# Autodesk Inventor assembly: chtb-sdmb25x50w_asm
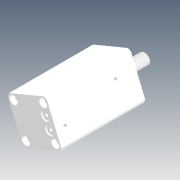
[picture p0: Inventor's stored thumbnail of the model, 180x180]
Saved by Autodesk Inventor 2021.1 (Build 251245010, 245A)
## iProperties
Company: Microsoft
Created: 2018-05
Part Number: chtb-sdmb25x50w_asm
Description: STEP AP214
Document SubType Name: Assembly
Designer: user
Title: chtb-sdmb25x50w_asm.STEP
Author: Windows
Revision Number: ÈÎºÎ
Sending System: SolidWorks 2015
Preprocessor: SwSTEP 2.0
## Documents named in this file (4)
- D:\Vault_2016\Projekty\Clamptek\Hydraulic\CHTB\CHTB-25\Inventor\chtb-sdmb25x50w\chtb-sdmb25x50w_asm.iam
- D:\Vault_2016\Projekty\Clamptek\Hydraulic\CHTB\CHTB-25\Inventor\chtb-sdmb25x50w\CHTB-25QG.ipt
- D:\Vault_2016\Projekty\Clamptek\Hydraulic\CHTB\CHTB-25\Inventor\chtb-sdmb25x50w\CHTB-SDMB25X50NBT.ipt
- D:\Vault_2016\Projekty\Clamptek\Hydraulic\CHTB\CHTB-25\Inventor\chtb-sdmb25x50w\CHTB-SDMB25X50WHSG.ipt
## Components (3 placed, 3 different names)
1. CHTB-25QG_1
2. CHTB-SDMB25X50NBT_2
3. CHTB-SDMB25X50WHSG_3
